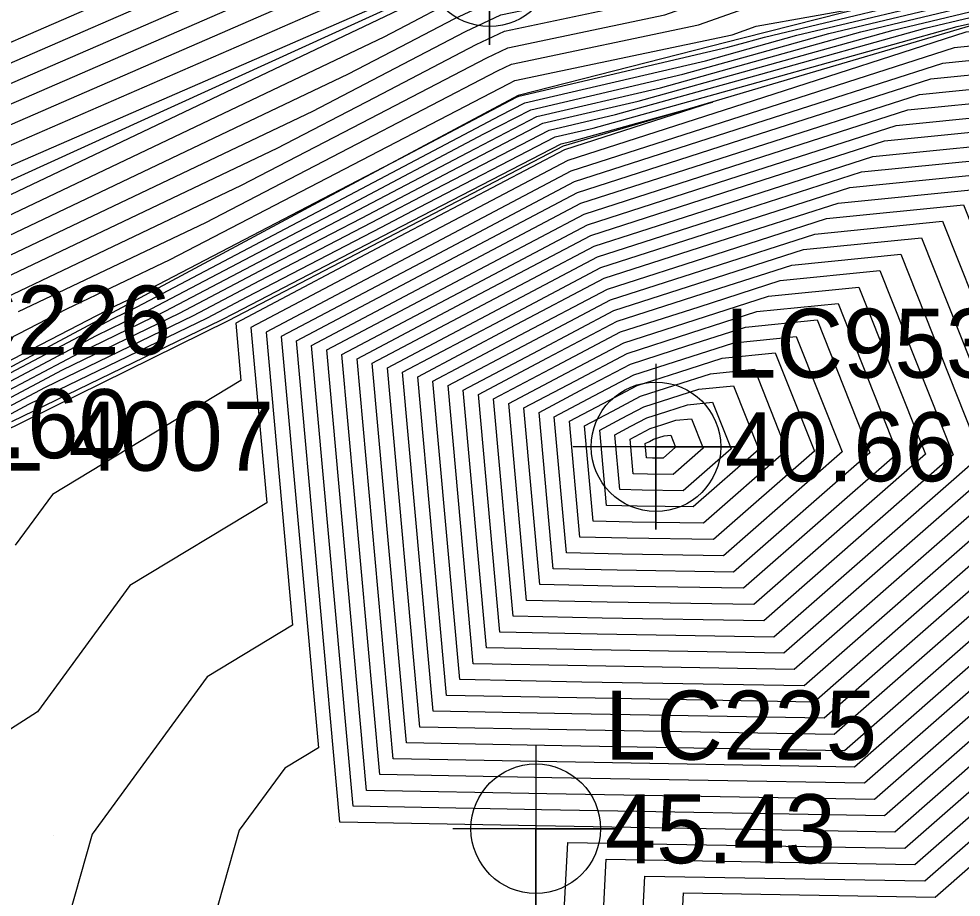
# Model space of a CAD drawing. Extents: x 2188792 to 2191981, y 386090 to 389710.
# Drawn here: x 2190178.31 to 2190212.42, y 387897.96 to 387929.77 of the extents above; entities that cross this region are included whole.
import ezdxf

# ---------------------------------------------------------------- set-up
doc = ezdxf.new("R2010")
doc.units = 0
for name, color, linetype in [('DTM Contours Major', 7, 'Continuous'), ('DTM Contours Minor', 7, 'Continuous'), ('Exist DTM Breakline Underwater', 7, 'Continuous'), ('Exist DTM Breakline Underwater Cogo Comment', 7, 'Continuous'), ('Exist DTM Breakline Underwater Cogo Point CELL', 7, 'Continuous'), ('Exist DTM QL2 LIDAR Elevation Point', 7, 'Continuous'), ('Exist DTM Regular Point Underwater CELL', 7, 'Continuous'), ('Exist DTM Regular Point Underwater Cogo Elevation', 7, 'Continuous'), ('Exist DTM Regular Point Underwater Cogo Number', 7, 'Continuous'), ('PH Exist DTM Breakline', 7, 'Continuous')]:
    doc.layers.add(name, color=color, linetype=linetype)

msp = doc.modelspace()

# ---------------------------------------------------------------- linework, layer by layer
at = {"layer": 'DTM Contours Major'}
for points in [[(2190243.465, 387950.942), (2190236.16, 387948.641), (2190229.647, 387946.589), (2190224.024, 387945.428), (2190217.646, 387943.561), (2190216.945, 387944.409), (2190212.415, 387943.221), (2190212.19, 387941.963), (2190203.611, 387938.301), (2190198.377, 387936.644), (2190193.887, 387935.221), (2190192.821, 387934.763), (2190189.103, 387932.693), (2190185.528, 387930.702), (2190172.055, 387924.838)], [(2190174.772, 387918.95), (2190187.655, 387925.086), (2190191.189, 387926.924), (2190194.861, 387928.834), (2190195.881, 387929.317), (2190200.477, 387930.285), (2190209.419, 387933.465), (2190214.208, 387934.324), (2190215.059, 387933.111), (2190219.916, 387934.166), (2190219.005, 387935.394), (2190218.404, 387938.199), (2190226.213, 387936.479), (2190233.879, 387937.854), (2190238.048, 387938.009), (2190238.066, 387937.699), (2190244.835, 387939.381)], [(2190175.323, 387915.538), (2190181.724, 387918.921), (2190182.593, 387919.342), (2190188.861, 387922.648), (2190189.628, 387923.046), (2190195.733, 387926.265), (2190196.621, 387926.724), (2190203.158, 387928.251), (2190204.711, 387928.684), (2190206.464, 387929.173), (2190212.686, 387930.663), (2190215.555, 387930.653), (2190220.883, 387931.821), (2190224.858, 387931.651), (2190229.111, 387932.482), (2190232.668, 387933.178), (2190238.216, 387935.813), (2190241.557, 387936.557)], [(2190174.341, 387884.909), (2190179.78, 387876.537), (2190184.682, 387879.952), (2190189.719, 387877.326), (2190192.093, 387885.619), (2190199.916, 387886.43), (2190200.828, 387887.573), (2190201.355, 387888.233), (2190200.535, 387890.18), (2190200.972, 387898.729), (2190211.107, 387898.557), (2190228.203, 387913.529), (2190222.305, 387928.372), (2190230.642, 387926.831), (2190238.626, 387930.623), (2190241.69, 387930.853)], [(2190177.058, 387914.963), (2190178.663, 387915.811), (2190185.133, 387918.946), (2190186.57, 387919.704), (2190191.44, 387922.226), (2190192.784, 387922.935), (2190197.72, 387925.492), (2190199.1, 387925.814), (2190205.286, 387927.539), (2190212.276, 387929.488), (2190212.754, 387929.602), (2190215.704, 387929.592), (2190212.585, 387929.28), (2190205.259, 387926.922), (2190198.174, 387924.643), (2190192.424, 387921.607), (2190186.705, 387918.588), (2190187.278, 387912.24), (2190182.327, 387909.245), (2190178.981, 387904.678), (2190176.674, 387903.202)], [(2190197.414, 387901.701), (2190190.892, 387901.83), (2190189.45, 387917.78), (2190194.099, 387920.234), (2190198.772, 387922.701), (2190204.531, 387924.554), (2190210.485, 387926.47), (2190217.801, 387927.203), (2190223.179, 387913.668), (2190209.283, 387901.5), (2190197.414, 387901.701)], [(2190198.325, 387904.597), (2190193.305, 387904.696), (2190192.195, 387916.972), (2190195.773, 387918.861), (2190199.37, 387920.76), (2190203.803, 387922.186), (2190208.385, 387923.661), (2190214.016, 387924.225), (2190218.156, 387913.807), (2190207.46, 387904.442), (2190198.325, 387904.597)], [(2190199.236, 387907.493), (2190195.718, 387907.562), (2190194.941, 387916.165), (2190197.448, 387917.488), (2190199.969, 387918.819), (2190203.074, 387919.818), (2190206.286, 387920.851), (2190210.231, 387921.246), (2190213.132, 387913.947), (2190205.637, 387907.384), (2190199.236, 387907.493)], [(2190200.147, 387910.389), (2190198.132, 387910.429), (2190197.686, 387915.357), (2190199.123, 387916.115), (2190200.567, 387916.877), (2190202.346, 387917.45), (2190204.186, 387918.042), (2190206.446, 387918.268), (2190208.108, 387914.086), (2190203.814, 387910.326), (2190200.147, 387910.389)], [(2190201.058, 387913.285), (2190200.545, 387913.295), (2190200.432, 387914.549), (2190200.797, 387914.742), (2190201.165, 387914.936), (2190201.618, 387915.082), (2190202.086, 387915.232), (2190202.661, 387915.29), (2190203.084, 387914.226), (2190201.991, 387913.269), (2190201.058, 387913.285)]]:
    msp.add_lwpolyline(points, dxfattribs=at)
at = {"layer": 'DTM Contours Minor'}
for points in [[(2190243.044, 387951.478), (2190237.242, 387949.866), (2190234.984, 387949.155), (2190227.762, 387946.88), (2190225.322, 387946.376), (2190217.734, 387944.155), (2190217.33, 387944.644), (2190211.391, 387943.086), (2190211.242, 387942.254), (2190205.567, 387939.832), (2190199.096, 387937.782), (2190193.543, 387936.023), (2190192.735, 387935.675), (2190188.149, 387933.122), (2190183.739, 387930.667), (2190173.274, 387926.112)], [(2190242.568, 387951.7), (2190235.104, 387949.627), (2190234.431, 387949.496), (2190226.52, 387948.609), (2190226.182, 387948.546), (2190226.23, 387947.193), (2190222.987, 387946.261), (2190217.822, 387944.749), (2190217.715, 387944.878), (2190210.367, 387942.951), (2190210.294, 387942.545), (2190207.523, 387941.362), (2190199.814, 387938.92), (2190193.199, 387936.824), (2190192.648, 387936.588), (2190187.195, 387933.551), (2190181.951, 387930.632), (2190174.494, 387927.386)], [(2190243.847, 387950.177), (2190237.337, 387948.126), (2190231.533, 387946.298), (2190222.725, 387944.479), (2190217.559, 387942.967), (2190216.56, 387944.175), (2190213.439, 387943.356), (2190213.139, 387941.672), (2190201.654, 387936.771), (2190197.659, 387935.505), (2190194.231, 387934.419), (2190192.908, 387933.851), (2190190.057, 387932.264), (2190187.316, 387930.737), (2190170.835, 387923.564)], [(2190244.228, 387949.412), (2190238.513, 387947.612), (2190233.418, 387946.007), (2190221.427, 387943.531), (2190217.471, 387942.373), (2190216.176, 387943.941), (2190214.464, 387943.492), (2190214.087, 387941.382), (2190199.698, 387935.241), (2190196.941, 387934.367), (2190194.575, 387933.618), (2190192.995, 387932.939), (2190191.011, 387931.835), (2190189.104, 387930.773), (2190169.615, 387922.29)], [(2190239.69, 387947.098), (2190235.303, 387945.716), (2190220.129, 387942.582), (2190217.384, 387941.779), (2190215.791, 387943.706), (2190215.488, 387943.627), (2190215.035, 387941.091), (2190197.741, 387933.71), (2190196.222, 387933.229), (2190194.919, 387932.816), (2190193.081, 387932.027), (2190191.965, 387931.405), (2190190.892, 387930.808), (2190168.395, 387921.016)], [(2190240.867, 387946.584), (2190237.189, 387945.425), (2190218.831, 387941.634), (2190217.296, 387941.185), (2190216.273, 387942.423), (2190215.983, 387940.8), (2190195.785, 387932.18), (2190195.504, 387932.091), (2190195.263, 387932.015), (2190193.168, 387931.115), (2190192.919, 387930.976), (2190192.68, 387930.843), (2190167.175, 387919.742)], [(2190167.739, 387918.52), (2190192.822, 387930.467), (2190193.059, 387930.59), (2190193.305, 387930.718), (2190195.37, 387931.698), (2190195.617, 387931.749), (2190215.316, 387938.755), (2190216.469, 387938.962), (2190218.21, 387936.481), (2190217.478, 387939.895), (2190219.357, 387939.481), (2190221.202, 387939.812), (2190241.932, 387940.58)], [(2190169.497, 387918.627), (2190191.531, 387929.122), (2190192.591, 387929.674), (2190193.694, 387930.247), (2190195.498, 387931.103), (2190196.832, 387931.383), (2190213.842, 387937.433), (2190215.903, 387937.803), (2190217.685, 387935.264), (2190218.699, 387935.484), (2190218.509, 387935.741), (2190217.71, 387939.471), (2190221.071, 387938.73), (2190224.371, 387939.322), (2190240.961, 387939.937)], [(2190171.256, 387918.735), (2190190.239, 387927.777), (2190192.124, 387928.757), (2190194.083, 387929.776), (2190195.625, 387930.507), (2190198.047, 387931.017), (2190212.368, 387936.11), (2190215.338, 387936.643), (2190216.809, 387934.546), (2190219.105, 387935.045), (2190218.674, 387935.625), (2190217.941, 387939.047), (2190222.785, 387937.98), (2190227.54, 387938.833), (2190239.99, 387939.294)], [(2190176.531, 387919.057), (2190186.364, 387923.741), (2190190.722, 387926.007), (2190195.25, 387928.362), (2190196.009, 387928.722), (2190201.693, 387929.919), (2190207.945, 387932.143), (2190213.642, 387933.165), (2190214.184, 387932.394), (2190220.321, 387933.727), (2190219.17, 387935.278), (2190218.635, 387937.775), (2190227.927, 387935.728), (2190237.048, 387937.365), (2190237.077, 387937.366), (2190237.077, 387937.364), (2190237.167, 387937.387), (2190244.751, 387939.075)], [(2190173.014, 387918.842), (2190188.947, 387926.431), (2190191.657, 387927.841), (2190194.472, 387929.305), (2190195.753, 387929.912), (2190199.262, 387930.651), (2190210.894, 387934.788), (2190214.773, 387935.484), (2190215.934, 387933.829), (2190219.51, 387934.606), (2190218.839, 387935.509), (2190218.172, 387938.623), (2190224.499, 387937.229), (2190230.71, 387938.344), (2190239.019, 387938.652)], [(2190178.289, 387919.165), (2190185.072, 387922.396), (2190190.254, 387925.091), (2190195.639, 387927.891), (2190196.136, 387928.127), (2190202.908, 387929.553), (2190206.471, 387930.82), (2190213.077, 387932.005), (2190213.308, 387931.676), (2190220.727, 387933.288), (2190219.335, 387935.163), (2190218.866, 387937.352), (2190228.468, 387935.236), (2190223.124, 387933.808), (2190228.954, 387934.948), (2190235.975, 387936.321), (2190237.355, 387936.977), (2190243.953, 387938.445)], [(2190173.758, 387916.019), (2190180.047, 387919.272), (2190183.78, 387921.05), (2190189.787, 387924.174), (2190196.028, 387927.42), (2190196.264, 387927.532), (2190204.123, 387929.187), (2190204.997, 387929.497), (2190209.081, 387930.23), (2190212.659, 387931.087), (2190212.983, 387931.086), (2190220.82, 387932.805), (2190221.99, 387932.754), (2190229.006, 387934.126), (2190234.873, 387935.273), (2190237.642, 387936.589), (2190243.154, 387937.816)], [(2190174.734, 387915.723), (2190181.806, 387919.38), (2190182.488, 387919.705), (2190189.319, 387923.258), (2190192.136, 387924.723), (2190196.323, 387926.931), (2190196.401, 387926.971), (2190203.97, 387928.739), (2190204.595, 387928.913), (2190205.302, 387929.11), (2190212.673, 387930.875), (2190214.269, 387930.87), (2190220.852, 387932.313), (2190223.424, 387932.203), (2190229.059, 387933.304), (2190233.77, 387934.226), (2190237.929, 387936.201), (2190242.356, 387937.186)], [(2190175.67, 387915.423), (2190181.112, 387918.299), (2190183.101, 387919.263), (2190188.402, 387922.059), (2190189.991, 387922.882), (2190195.144, 387925.599), (2190196.84, 387926.478), (2190202.346, 387927.764), (2190204.826, 387928.455), (2190207.627, 387929.236), (2190212.7, 387930.451), (2190216.841, 387930.436), (2190220.915, 387931.33), (2190226.292, 387931.099), (2190229.164, 387931.66), (2190231.565, 387932.13), (2190238.503, 387935.425), (2190240.759, 387935.927)], [(2190176.017, 387915.308), (2190180.5, 387917.677), (2190183.609, 387919.184), (2190187.944, 387921.47), (2190190.353, 387922.718), (2190194.554, 387924.933), (2190197.06, 387926.231), (2190201.535, 387927.276), (2190204.941, 387928.226), (2190208.789, 387929.299), (2190212.714, 387930.239), (2190218.127, 387930.22), (2190220.946, 387930.838), (2190227.727, 387930.547), (2190229.217, 387930.839), (2190230.462, 387931.082), (2190238.79, 387935.037)], [(2190176.364, 387915.193), (2190179.888, 387917.055), (2190184.117, 387919.105), (2190187.486, 387920.881), (2190190.715, 387922.554), (2190193.964, 387924.267), (2190197.28, 387925.985), (2190200.723, 387926.789), (2190205.056, 387927.997), (2190209.951, 387929.362), (2190212.727, 387930.027), (2190219.412, 387930.003), (2190220.977, 387930.346), (2190229.161, 387929.995), (2190229.269, 387930.017), (2190229.36, 387930.034), (2190239.077, 387934.649)], [(2190176.711, 387915.078), (2190179.276, 387916.433), (2190184.625, 387919.025), (2190187.028, 387920.292), (2190191.077, 387922.39), (2190193.374, 387923.601), (2190197.5, 387925.738), (2190199.911, 387926.301), (2190205.171, 387927.768), (2190211.113, 387929.425), (2190212.741, 387929.815), (2190220.698, 387929.787), (2190221.009, 387929.855), (2190222.766, 387929.779), (2190229.93, 387928.455), (2190238.872, 387932.703)], [(2190220.829, 387929.585), (2190212.165, 387928.718), (2190205.114, 387926.449), (2190198.294, 387924.254), (2190192.759, 387921.333), (2190187.254, 387918.426), (2190188.213, 387907.808), (2190185.129, 387905.942), (2190180.957, 387900.249), (2190179.676, 387895.729), (2190178.545, 387890.464), (2190178.528, 387889.202), (2190179.792, 387887.256), (2190184.138, 387890.284), (2190189.746, 387892.007), (2190191.026, 387891.843), (2190199.217, 387892.363), (2190199.573, 387899.336), (2190210.742, 387899.146), (2190227.198, 387913.556), (2190220.829, 387929.585)], [(2190220.072, 387928.99), (2190211.745, 387928.156), (2190204.968, 387925.975), (2190198.413, 387923.866), (2190193.094, 387921.058), (2190187.803, 387918.265), (2190189.148, 387903.377), (2190187.93, 387902.64), (2190186.283, 387900.391), (2190184.942, 387895.658), (2190189.754, 387897.137), (2190194.308, 387896.552), (2190198.013, 387896.787), (2190198.174, 387899.942), (2190210.377, 387899.734), (2190226.194, 387913.584), (2190220.072, 387928.99)], [(2190175.651, 387867.863), (2190179.787, 387869.805), (2190189.109, 387869.486), (2190189.727, 387869.59), (2190190.166, 387869.496), (2190193.604, 387870.228), (2190195.95, 387878.423), (2190200.065, 387878.85), (2190202.885, 387882.384), (2190204.513, 387884.424), (2190201.979, 387890.447), (2190202.371, 387898.123), (2190211.471, 387897.969), (2190229.208, 387913.501), (2190224.018, 387926.563), (2190231.354, 387925.207), (2190238.38, 387928.544), (2190241.077, 387928.746)], [(2190197.05, 387900.543), (2190189.926, 387900.684), (2190188.352, 387918.103), (2190193.429, 387920.783), (2190198.533, 387923.478), (2190204.822, 387925.502), (2190211.325, 387927.594), (2190219.315, 387928.394), (2190225.189, 387913.612), (2190210.013, 387900.323), (2190197.05, 387900.543)], [(2190197.232, 387901.122), (2190190.409, 387901.257), (2190188.901, 387917.942), (2190193.764, 387920.509), (2190198.653, 387923.09), (2190204.677, 387925.028), (2190210.905, 387927.032), (2190218.558, 387927.798), (2190224.184, 387913.64), (2190209.648, 387900.911), (2190197.232, 387901.122)], [(2190178.051, 387915.189), (2190185.641, 387918.867), (2190186.111, 387919.115), (2190191.802, 387922.063), (2190192.194, 387922.269), (2190197.94, 387925.245), (2190198.288, 387925.326), (2190203.419, 387926.757), (2190198.055, 387925.031), (2190192.089, 387921.882), (2190186.156, 387918.749), (2190186.343, 387916.672), (2190179.525, 387912.547), (2190178.179, 387910.71)], [(2190197.596, 387902.28), (2190191.374, 387902.403), (2190189.999, 387917.619), (2190194.434, 387919.96), (2190198.892, 387922.313), (2190204.385, 387924.081), (2190210.065, 387925.908), (2190217.044, 387926.607), (2190222.175, 387913.696), (2190208.919, 387902.088), (2190197.596, 387902.28)], [(2190197.778, 387902.86), (2190191.857, 387902.977), (2190190.548, 387917.457), (2190194.769, 387919.685), (2190199.012, 387921.925), (2190204.24, 387923.607), (2190209.645, 387925.346), (2190216.287, 387926.012), (2190221.17, 387913.724), (2190208.554, 387902.677), (2190197.778, 387902.86)], [(2190197.961, 387903.439), (2190192.34, 387903.55), (2190191.097, 387917.295), (2190195.104, 387919.41), (2190199.131, 387921.537), (2190204.094, 387923.133), (2190209.225, 387924.785), (2190215.53, 387925.416), (2190220.165, 387913.752), (2190208.19, 387903.265), (2190197.961, 387903.439)], [(2190198.143, 387904.018), (2190192.822, 387904.123), (2190191.646, 387917.134), (2190195.438, 387919.136), (2190199.251, 387921.148), (2190203.948, 387922.66), (2190208.805, 387924.223), (2190214.773, 387924.82), (2190219.16, 387913.779), (2190207.825, 387903.853), (2190198.143, 387904.018)], [(2190198.507, 387905.176), (2190193.788, 387905.27), (2190192.745, 387916.811), (2190196.108, 387918.587), (2190199.49, 387920.372), (2190203.657, 387921.713), (2190207.965, 387923.099), (2190213.259, 387923.629), (2190217.151, 387913.835), (2190207.096, 387905.03), (2190198.507, 387905.176)], [(2190198.689, 387905.755), (2190194.27, 387905.843), (2190193.294, 387916.649), (2190196.443, 387918.312), (2190199.61, 387919.983), (2190203.511, 387921.239), (2190207.545, 387922.537), (2190212.502, 387923.033), (2190216.146, 387913.863), (2190206.731, 387905.619), (2190198.689, 387905.755)], [(2190198.872, 387906.335), (2190194.753, 387906.416), (2190193.843, 387916.488), (2190196.778, 387918.037), (2190199.729, 387919.595), (2190203.366, 387920.765), (2190207.125, 387921.975), (2190211.745, 387922.438), (2190215.141, 387913.891), (2190206.367, 387906.207), (2190198.872, 387906.335)], [(2190199.054, 387906.914), (2190195.236, 387906.989), (2190194.392, 387916.326), (2190197.113, 387917.763), (2190199.849, 387919.207), (2190203.22, 387920.292), (2190206.706, 387921.413), (2190210.988, 387921.842), (2190214.136, 387913.919), (2190206.002, 387906.796), (2190199.054, 387906.914)], [(2190199.418, 387908.072), (2190196.201, 387908.136), (2190195.49, 387916.003), (2190197.783, 387917.213), (2190200.088, 387918.43), (2190202.929, 387919.344), (2190205.866, 387920.289), (2190209.474, 387920.651), (2190212.127, 387913.975), (2190205.273, 387907.973), (2190199.418, 387908.072)], [(2190199.6, 387908.651), (2190196.684, 387908.709), (2190196.039, 387915.841), (2190198.118, 387916.939), (2190200.208, 387918.042), (2190202.783, 387918.871), (2190205.446, 387919.727), (2190208.717, 387920.055), (2190211.122, 387914.003), (2190204.908, 387908.561), (2190199.6, 387908.651)], [(2190199.783, 387909.23), (2190197.166, 387909.282), (2190196.588, 387915.68), (2190198.453, 387916.664), (2190200.327, 387917.654), (2190202.637, 387918.397), (2190205.026, 387919.166), (2190207.96, 387919.459), (2190210.117, 387914.03), (2190204.544, 387909.15), (2190199.783, 387909.23)], [(2190199.965, 387909.81), (2190197.649, 387909.855), (2190197.137, 387915.518), (2190198.788, 387916.39), (2190200.447, 387917.266), (2190202.492, 387917.923), (2190204.606, 387918.604), (2190207.203, 387918.864), (2190209.113, 387914.058), (2190204.179, 387909.738), (2190199.965, 387909.81)], [(2190200.329, 387910.968), (2190198.614, 387911.002), (2190198.235, 387915.195), (2190199.458, 387915.84), (2190200.686, 387916.489), (2190202.2, 387916.976), (2190203.766, 387917.48), (2190205.689, 387917.673), (2190207.103, 387914.114), (2190203.45, 387910.915), (2190200.329, 387910.968)], [(2190200.511, 387911.547), (2190199.097, 387911.575), (2190198.784, 387915.034), (2190199.793, 387915.566), (2190200.806, 387916.101), (2190202.055, 387916.503), (2190203.346, 387916.918), (2190204.932, 387917.077), (2190206.098, 387914.142), (2190203.085, 387911.503), (2190200.511, 387911.547)], [(2190200.694, 387912.126), (2190199.58, 387912.148), (2190199.334, 387914.872), (2190200.127, 387915.291), (2190200.926, 387915.713), (2190201.909, 387916.029), (2190202.926, 387916.356), (2190204.175, 387916.481), (2190205.094, 387914.17), (2190202.721, 387912.092), (2190200.694, 387912.126)], [(2190200.876, 387912.705), (2190200.062, 387912.721), (2190199.883, 387914.711), (2190200.462, 387915.017), (2190201.045, 387915.324), (2190201.763, 387915.555), (2190202.506, 387915.794), (2190203.418, 387915.886), (2190204.089, 387914.198), (2190202.356, 387912.68), (2190200.876, 387912.705)], [(2190201.24, 387913.864), (2190201.028, 387913.868), (2190200.981, 387914.387), (2190201.132, 387914.467), (2190201.284, 387914.548), (2190201.472, 387914.608), (2190201.666, 387914.67), (2190201.904, 387914.694), (2190202.079, 387914.253), (2190201.627, 387913.857), (2190201.24, 387913.864)]]:
    msp.add_lwpolyline(points, dxfattribs=at)
at = {"layer": 'Exist DTM Breakline Underwater'}
msp.add_lwpolyline([(2190165.897, 387918.407), (2190195.341, 387931.833), (2190217.185, 387940.432), (2190258.084, 387945.215), (2190309.218, 387932.714), (2190343.089, 387929.481), (2190375.21, 387918.126)], dxfattribs=at)
at = {"layer": 'Exist DTM Breakline Underwater Cogo Point CELL'}
msp.add_lwpolyline([(2190195.341, 387934.833), (2190195.341, 387928.833), (2190195.341, 387931.833), (2190198.341, 387931.833), (2190192.341, 387931.833)], dxfattribs=at)
msp.add_circle((2190195.341, 387931.833), 2.344, dxfattribs=at)
at = {"layer": 'Exist DTM QL2 LIDAR Elevation Point'}
for p, q in [((2190189.759, 387900.485), (2190189.759, 387900.485)), ((2190179.574, 387900.212), (2190179.574, 387900.212))]:
    msp.add_line(p, q, dxfattribs=at)
at = {"layer": 'Exist DTM Regular Point Underwater CELL'}
for points in [[(2190201.369, 387917.273), (2190201.369, 387911.273), (2190201.369, 387914.273), (2190204.369, 387914.273), (2190198.369, 387914.273)], [(2190197.018, 387903.442), (2190197.018, 387897.442), (2190197.018, 387900.442), (2190200.018, 387900.442), (2190194.018, 387900.442)]]:
    msp.add_lwpolyline(points, dxfattribs=at)
for centre in [(2190201.369, 387914.273), (2190197.018, 387900.442)]:
    msp.add_circle(centre, 2.344, dxfattribs=at)
at = {"layer": 'PH Exist DTM Breakline'}
for points in [[(2190245.208, 387939.435), (2190237.07, 387937.362), (2190228.932, 387935.288), (2190220.794, 387933.215), (2190212.656, 387931.141), (2190204.518, 387929.068), (2190196.38, 387926.994), (2190189.289, 387923.199), (2190182.199, 387919.404), (2190175.109, 387915.609), (2190167.285, 387912.244), (2190159.46, 387908.88), (2190151.636, 387905.515), (2190141, 387899.082), (2190133.702, 387893.484)], [(2190301.394, 387927.26), (2190292.177, 387929.22), (2190282.959, 387931.179), (2190276.211, 387932.556), (2190269.463, 387933.933), (2190258.068, 387935.251), (2190247.423, 387935.199), (2190239.099, 387934.619), (2190229.273, 387929.952), (2190221.017, 387929.733), (2190212.76, 387929.514), (2190205.387, 387927.338), (2190198.014, 387925.162), (2190191.951, 387921.995), (2190185.888, 387918.828), (2190177.639, 387914.771), (2190169.39, 387910.713), (2190163.13, 387908.28), (2190156.87, 387905.846), (2190150.61, 387903.413), (2190143.688, 387898.862), (2190136.766, 387894.311)]]:
    msp.add_lwpolyline(points, dxfattribs=at)

# ---------------------------------------------------------------- texts
at = {"layer": 'Exist DTM Breakline Underwater Cogo Comment'}
msp.add_text('*BL*BL 4007', height=2.5, dxfattribs=at).set_placement((2190168.397, 387913.407))
at = {"layer": 'Exist DTM Regular Point Underwater Cogo Elevation'}
for s, p in [('44.60', (2190173.963, 387913.859)), ('40.66', (2190203.869, 387913.023)), ('45.43', (2190199.518, 387899.192))]:
    msp.add_text(s, height=2.5, dxfattribs=at).set_placement(p)
at = {"layer": 'Exist DTM Regular Point Underwater Cogo Number'}
for s, p in [('LC226', (2190173.963, 387917.609)), ('LC953', (2190203.869, 387916.773)), ('LC225', (2190199.518, 387902.942))]:
    msp.add_text(s, height=2.5, dxfattribs=at).set_placement(p)

doc.saveas('drawing.dxf')
